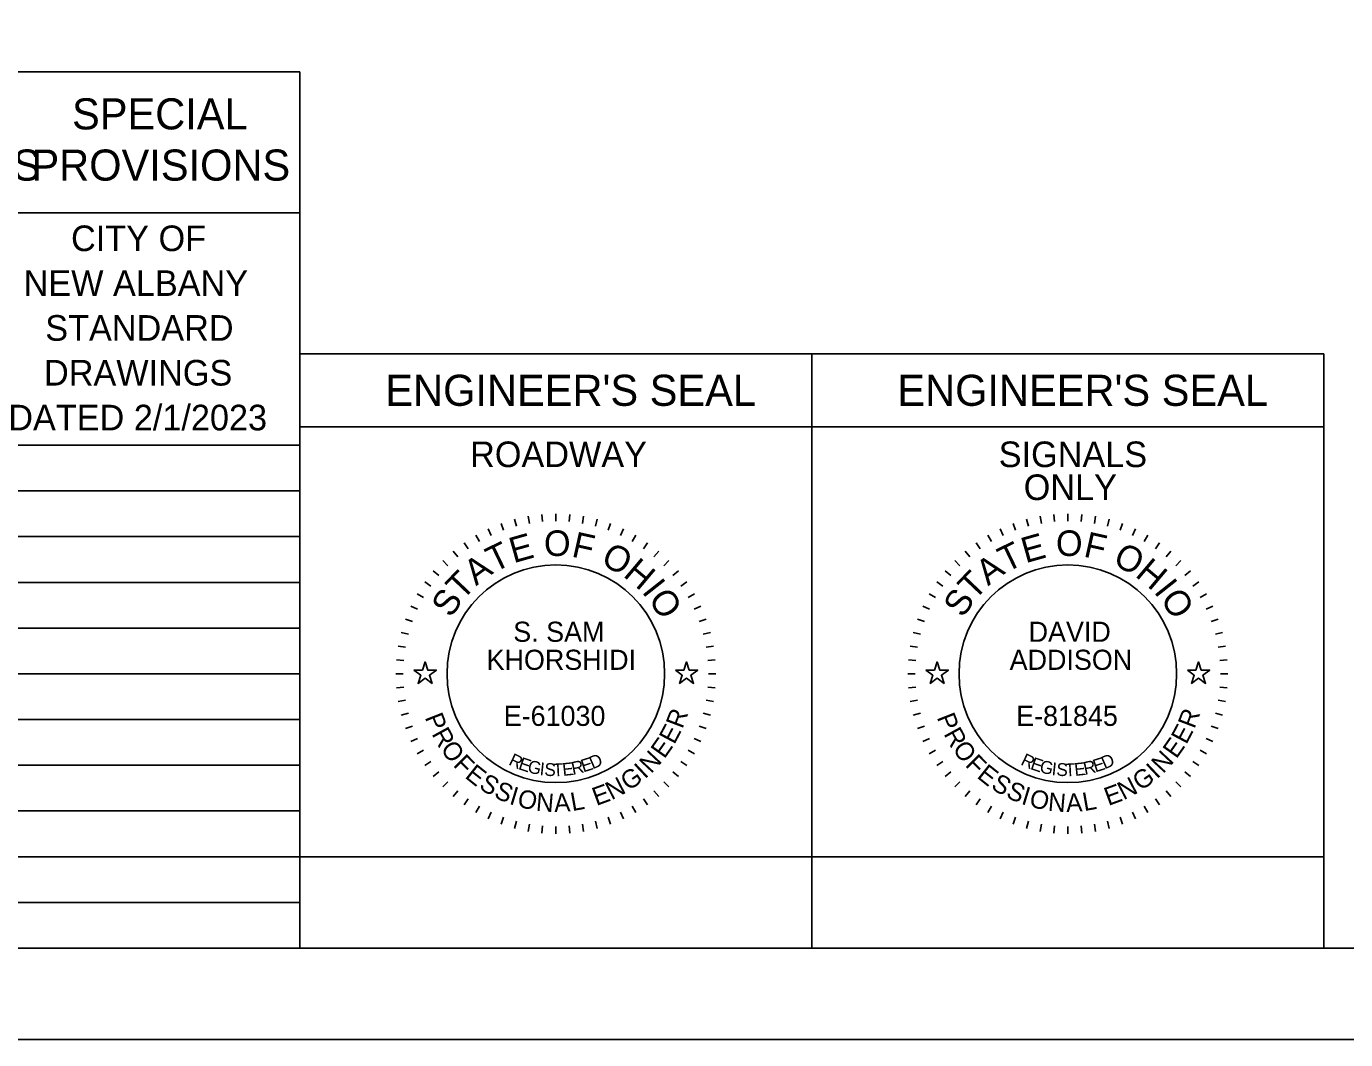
# Model space of a CAD drawing. Extents: x 0 to 91.3, y -0.7 to 22.
# Drawn here: x 22.1 to 29.32, y 0 to 5.54 of the extents above; entities that cross this region are included whole.
import ezdxf

# ---------------------------------------------------------------- set-up
doc = ezdxf.new("R2010")
doc.units = 0
for name, color, linetype in [('Default', 7, 'Continuous'), ('SH_Border', 7, 'Continuous'), ('SH_Cut_Line', 7, 'Continuous'), ('SH_Data', 7, 'Continuous'), ('SH_Text', 7, 'Continuous')]:
    doc.layers.add(name, color=color, linetype=linetype)

msp = doc.modelspace()

# ---------------------------------------------------------------- linework, layer by layer
at = {"layer": 'Default'}
for points in [[(24.2236, 2.02), (24.2705, 2.02), (24.285, 2.0645), (24.2995, 2.02), (24.3464, 2.02), (24.3085, 1.9924), (24.323, 1.9478), (24.285, 1.9754), (24.247, 1.9478), (24.2615, 1.9924)], [(25.6536, 2.02), (25.7005, 2.02), (25.715, 2.0645), (25.7295, 2.02), (25.7764, 2.02), (25.7385, 1.9924), (25.753, 1.9478), (25.715, 1.9754), (25.677, 1.9478), (25.6915, 1.9924)], [(27.0236, 2.02), (27.0705, 2.02), (27.085, 2.0645), (27.0995, 2.02), (27.1464, 2.02), (27.1085, 1.9924), (27.123, 1.9478), (27.085, 1.9754), (27.047, 1.9478), (27.0615, 1.9924)], [(28.4536, 2.02), (28.5005, 2.02), (28.515, 2.0645), (28.5295, 2.02), (28.5764, 2.02), (28.5385, 1.9924), (28.553, 1.9478), (28.515, 1.9754), (28.477, 1.9478), (28.4915, 1.9924)]]:
    msp.add_lwpolyline(points, close=True, dxfattribs=at)
at = {"layer": 'SH_Border'}
msp.add_lwpolyline([(1.5, 21.5), (33.5, 21.5), (33.5, 0.5), (1.5, 0.5)], close=True, dxfattribs=at)
at = {"layer": 'SH_Cut_Line'}
msp.add_lwpolyline([(0, 0), (34, 0), (34, 22), (0, 22)], close=True, dxfattribs=at)
at = {"layer": 'SH_Data'}
for p, q in [((10.15, 5.2917), (23.6, 5.2917)), ((23.6, 0.5), (23.6, 5.2917)), ((10.15, 4.5209), (23.6, 4.5209)), ((23.6, 0.5), (23.6, 3.75)), ((23.6, 3.75), (26.4, 3.75)), ((26.4, 3.75), (26.4, 0.5)), ((26.4, 0.5), (26.4, 3.75)), ((26.4, 3.75), (29.2, 3.75)), ((29.2, 3.75), (29.2, 0.5)), ((23.6, 3.35), (26.4, 3.35)), ((26.4, 3.35), (29.2, 3.35)), ((10.15, 3.25), (23.6, 3.25)), ((10.15, 3), (23.6, 3)), ((24.7007, 2.8222), (24.7144, 2.7846)), ((24.7735, 2.8452), (24.7839, 2.8065)), ((24.8481, 2.8617), (24.855, 2.8223)), ((24.9237, 2.8717), (24.9272, 2.8318)), ((25, 2.875), (25, 2.835)), ((25.0763, 2.8717), (25.0728, 2.8318)), ((25.1519, 2.8617), (25.145, 2.8223)), ((25.2265, 2.8452), (25.2161, 2.8065)), ((25.2993, 2.8222), (25.2856, 2.7846)), ((27.5007, 2.8222), (27.5144, 2.7846)), ((27.5735, 2.8452), (27.5839, 2.8065)), ((27.6481, 2.8617), (27.655, 2.8223)), ((27.7237, 2.8717), (27.7272, 2.8318)), ((27.8, 2.875), (27.8, 2.835)), ((27.8763, 2.8717), (27.8728, 2.8318)), ((27.9519, 2.8617), (27.945, 2.8223)), ((28.0265, 2.8452), (28.0161, 2.8065)), ((28.0993, 2.8222), (28.0856, 2.7846)), ((10.15, 2.75), (23.6, 2.75)), ((24.5625, 2.7578), (24.5825, 2.7231)), ((24.6302, 2.793), (24.6471, 2.7568)), ((25.3698, 2.793), (25.3529, 2.7568)), ((25.4375, 2.7578), (25.4175, 2.7231)), ((27.3625, 2.7578), (27.3825, 2.7231)), ((27.4302, 2.793), (27.4471, 2.7568)), ((28.1698, 2.793), (28.1529, 2.7568)), ((28.2375, 2.7578), (28.2175, 2.7231)), ((24.4376, 2.6703), (24.4633, 2.6396)), ((24.4981, 2.7168), (24.5211, 2.684)), ((25.5019, 2.7168), (25.4789, 2.684)), ((25.5624, 2.6703), (25.5367, 2.6396)), ((27.2376, 2.6703), (27.2633, 2.6396)), ((27.2981, 2.7168), (27.3211, 2.684)), ((28.3019, 2.7168), (28.2789, 2.684)), ((28.3624, 2.6703), (28.3367, 2.6396)), ((24.3813, 2.6187), (24.4096, 2.5904)), ((25.6187, 2.6187), (25.5904, 2.5904)), ((27.1813, 2.6187), (27.2096, 2.5904)), ((28.4187, 2.6187), (28.3904, 2.5904)), ((24.3297, 2.5624), (24.3604, 2.5367)), ((25.6703, 2.5624), (25.6396, 2.5367)), ((27.1297, 2.5624), (27.1604, 2.5367)), ((28.4703, 2.5624), (28.4396, 2.5367)), ((10.15, 2.5), (23.6, 2.5)), ((24.2832, 2.5019), (24.316, 2.4789)), ((25.7168, 2.5019), (25.684, 2.4789)), ((27.0832, 2.5019), (27.116, 2.4789)), ((28.5168, 2.5019), (28.484, 2.4789)), ((24.2422, 2.4375), (24.2769, 2.4175)), ((25.7578, 2.4375), (25.7231, 2.4175)), ((27.0422, 2.4375), (27.0769, 2.4175)), ((28.5578, 2.4375), (28.5231, 2.4175)), ((24.207, 2.3698), (24.2432, 2.3529)), ((25.793, 2.3698), (25.7568, 2.3529)), ((27.007, 2.3698), (27.0432, 2.3529)), ((28.593, 2.3698), (28.5568, 2.3529)), ((10.15, 2.25), (23.6, 2.25)), ((24.1778, 2.2993), (24.2154, 2.2856)), ((25.8222, 2.2993), (25.7846, 2.2856)), ((26.9778, 2.2993), (27.0154, 2.2856)), ((28.6222, 2.2993), (28.5846, 2.2856)), ((24.1548, 2.2265), (24.1935, 2.2161)), ((25.8452, 2.2265), (25.8065, 2.2161)), ((26.9548, 2.2265), (26.9935, 2.2161)), ((28.6452, 2.2265), (28.6065, 2.2161)), ((24.1383, 2.1519), (24.1777, 2.145)), ((25.8617, 2.1519), (25.8223, 2.145)), ((26.9383, 2.1519), (26.9777, 2.145)), ((28.6617, 2.1519), (28.6223, 2.145)), ((24.1283, 2.0763), (24.1682, 2.0728)), ((25.8717, 2.0763), (25.8318, 2.0728)), ((26.9283, 2.0763), (26.9682, 2.0728)), ((28.6717, 2.0763), (28.6318, 2.0728)), ((10.15, 2), (23.6, 2)), ((24.125, 2), (24.165, 2)), ((25.875, 2), (25.835, 2)), ((26.925, 2), (26.965, 2)), ((28.675, 2), (28.635, 2)), ((24.1283, 1.9237), (24.1682, 1.9272)), ((25.8717, 1.9237), (25.8318, 1.9272)), ((26.9283, 1.9237), (26.9682, 1.9272)), ((28.6717, 1.9237), (28.6318, 1.9272)), ((24.1383, 1.8481), (24.1777, 1.855)), ((25.8617, 1.8481), (25.8223, 1.855)), ((26.9383, 1.8481), (26.9777, 1.855)), ((28.6617, 1.8481), (28.6223, 1.855)), ((10.15, 1.75), (23.6, 1.75)), ((24.1548, 1.7735), (24.1935, 1.7839)), ((25.8452, 1.7735), (25.8065, 1.7839)), ((26.9548, 1.7735), (26.9935, 1.7839)), ((28.6452, 1.7735), (28.6065, 1.7839)), ((24.1778, 1.7007), (24.2154, 1.7144)), ((25.8222, 1.7007), (25.7846, 1.7144)), ((26.9778, 1.7007), (27.0154, 1.7144)), ((28.6222, 1.7007), (28.5846, 1.7144)), ((24.207, 1.6302), (24.2432, 1.6471)), ((25.793, 1.6302), (25.7568, 1.6471)), ((27.007, 1.6302), (27.0432, 1.6471)), ((28.593, 1.6302), (28.5568, 1.6471)), ((24.2422, 1.5625), (24.2769, 1.5825)), ((24.2832, 1.4981), (24.316, 1.5211)), ((25.7168, 1.4981), (25.684, 1.5211)), ((25.7578, 1.5625), (25.7231, 1.5825)), ((27.0422, 1.5625), (27.0769, 1.5825)), ((27.0832, 1.4981), (27.116, 1.5211)), ((28.5168, 1.4981), (28.484, 1.5211)), ((28.5578, 1.5625), (28.5231, 1.5825)), ((10.15, 1.5), (23.6, 1.5)), ((24.3297, 1.4376), (24.3604, 1.4633)), ((25.6703, 1.4376), (25.6396, 1.4633)), ((27.1297, 1.4376), (27.1604, 1.4633)), ((28.4703, 1.4376), (28.4396, 1.4633)), ((24.3813, 1.3813), (24.4096, 1.4096)), ((25.6187, 1.3813), (25.5904, 1.4096)), ((27.1813, 1.3813), (27.2096, 1.4096)), ((28.4187, 1.3813), (28.3904, 1.4096)), ((24.4376, 1.3297), (24.4633, 1.3604)), ((24.4981, 1.2832), (24.5211, 1.316)), ((25.5019, 1.2832), (25.4789, 1.316)), ((25.5624, 1.3297), (25.5367, 1.3604)), ((27.2376, 1.3297), (27.2633, 1.3604)), ((27.2981, 1.2832), (27.3211, 1.316)), ((28.3019, 1.2832), (28.2789, 1.316)), ((28.3624, 1.3297), (28.3367, 1.3604)), ((10.15, 1.25), (23.6, 1.25)), ((24.5625, 1.2422), (24.5825, 1.2769)), ((24.6302, 1.207), (24.6471, 1.2432)), ((25.3698, 1.207), (25.3529, 1.2432)), ((25.4375, 1.2422), (25.4175, 1.2769)), ((27.3625, 1.2422), (27.3825, 1.2769)), ((27.4302, 1.207), (27.4471, 1.2432)), ((28.1698, 1.207), (28.1529, 1.2432)), ((28.2375, 1.2422), (28.2175, 1.2769)), ((24.7007, 1.1778), (24.7144, 1.2154)), ((24.7735, 1.1548), (24.7839, 1.1935)), ((24.8481, 1.1383), (24.855, 1.1777)), ((24.9237, 1.1283), (24.9272, 1.1682)), ((25, 1.125), (25, 1.165)), ((25.0763, 1.1283), (25.0728, 1.1682)), ((25.1519, 1.1383), (25.145, 1.1777)), ((25.2265, 1.1548), (25.2161, 1.1935)), ((25.2993, 1.1778), (25.2856, 1.2154)), ((27.5007, 1.1778), (27.5144, 1.2154)), ((27.5735, 1.1548), (27.5839, 1.1935)), ((27.6481, 1.1383), (27.655, 1.1777)), ((27.7237, 1.1283), (27.7272, 1.1682)), ((27.8, 1.125), (27.8, 1.165)), ((27.8763, 1.1283), (27.8728, 1.1682)), ((27.9519, 1.1383), (27.945, 1.1777)), ((28.0265, 1.1548), (28.0161, 1.1935)), ((28.0993, 1.1778), (28.0856, 1.2154)), ((10.15, 1), (23.6, 1)), ((10.15, 0.75), (23.6, 0.75)), ((23.6, 0.5), (26.4, 0.5)), ((26.4, 0.5), (29.2, 0.5))]:
    msp.add_line(p, q, dxfattribs=at)
for points in [[(23.6, 0.5), (23.6, 1), (26.4, 1), (26.4, 0.5)], [(26.4, 0.5), (26.4, 1), (29.2, 1), (29.2, 0.5)]]:
    msp.add_lwpolyline(points, close=True, dxfattribs=at)
for centre in [(25, 2), (27.8, 2)]:
    msp.add_circle(centre, 0.595, dxfattribs=at)

# ---------------------------------------------------------------- texts
for s, height, p in [("ENGINEER'S SEAL", 0.17, (24.0676, 3.465)), ("ENGINEER'S SEAL", 0.17, (26.8676, 3.465)), ('ROADWAY', 0.14, (24.5311, 3.13)), ('SIGNALS', 0.14, (27.4219, 3.13)), ('ONLY', 0.14, (27.5585, 2.95)), ('S. SAM', 0.11, (24.7671, 2.1749)), ('DAVID', 0.11, (27.5854, 2.1749)), ('KHORSHIDI', 0.11, (24.6213, 2.0216)), ('ADDISON', 0.11, (27.4816, 2.0216)), ('E-61030', 0.11, (24.7149, 1.7151)), ('E-81845', 0.11, (27.5173, 1.7151))]:
    msp.add_text(s, height=height, dxfattribs=at).set_placement(p)
for s, height, rotation, p in [('E', 0.14, 15.75706, (24.7684, 2.6038)), ('O', 0.14, 359.78119, (24.9347, 2.6443)), ('F', 0.14, 347.43619, (25.0811, 2.6417)), ('E', 0.14, 15.75706, (27.5684, 2.6038)), ('O', 0.14, 359.78119, (27.7347, 2.6443)), ('F', 0.14, 347.43619, (27.8811, 2.6417)), ('T', 0.14, 25.71674, (24.6616, 2.5518)), ('O', 0.14, 332.25863, (25.2398, 2.6015)), ('T', 0.14, 25.71674, (27.4616, 2.5518)), ('O', 0.14, 332.25863, (28.0398, 2.6015)), ('A', 0.14, 36.47472, (24.5634, 2.4781)), ('H', 0.14, 319.91363, (25.3632, 2.5361)), ('A', 0.14, 36.47472, (27.3634, 2.4781)), ('H', 0.14, 319.91363, (28.1632, 2.5361)), ('T', 0.14, 46.4344, (24.4883, 2.3964)), ('T', 0.14, 46.4344, (27.2883, 2.3964)), ('S', 0.14, 57.19238, (24.4281, 2.3014)), ('I', 0.14, 308.36695, (25.4665, 2.4483)), ('O', 0.14, 303.14906, (25.5021, 2.4089)), ('S', 0.14, 57.19238, (27.2281, 2.3014)), ('I', 0.14, 308.36695, (28.2665, 2.4483)), ('O', 0.14, 303.14906, (28.3021, 2.4089)), ('R', 0.1, 69.23216, (25.6919, 1.6954)), ('R', 0.1, 69.23216, (28.4919, 1.6954)), ('P', 0.1, 291.49398, (24.2823, 1.7621)), ('P', 0.1, 291.49398, (27.0823, 1.7621)), ('R', 0.1, 298.73106, (24.319, 1.6717)), ('E', 0.1, 61.99508, (25.6476, 1.6098)), ('R', 0.1, 298.73106, (27.119, 1.6717)), ('E', 0.1, 61.99508, (28.4476, 1.6098)), ('O', 0.1, 306.46664, (24.3655, 1.5883)), ('E', 0.1, 54.75801, (25.5933, 1.5314)), ('O', 0.1, 306.46664, (27.1655, 1.5883)), ('E', 0.1, 54.75801, (28.3933, 1.5314)), ('F', 0.1, 314.7068, (24.4343, 1.4983)), ('R', 0.07, 334.48695, (24.7375, 1.5051)), ('E', 0.07, 341.03996, (24.7906, 1.4801)), ('G', 0.07, 347.47515, (24.8414, 1.4618)), ('I', 0.07, 353.78581, (24.9091, 1.4468)), ('E', 0.07, 6.01169, (25.0389, 1.4412)), ('R', 0.07, 11.91844, (25.0925, 1.4474)), ('E', 0.07, 17.68363, (25.1498, 1.4602)), ('D', 0.07, 23.30524, (25.201, 1.477)), ('N', 0.1, 47.02243, (25.5202, 1.4508)), ('F', 0.1, 314.7068, (27.2343, 1.4983)), ('R', 0.07, 334.48695, (27.5375, 1.5051)), ('E', 0.07, 341.03996, (27.5906, 1.4801)), ('G', 0.07, 347.47515, (27.6414, 1.4618)), ('I', 0.07, 353.78581, (27.7091, 1.4468)), ('E', 0.07, 6.01169, (27.8389, 1.4412)), ('R', 0.07, 11.91844, (27.8925, 1.4474)), ('E', 0.07, 17.68363, (27.9498, 1.4602)), ('D', 0.07, 23.30524, (28.001, 1.477)), ('N', 0.1, 47.02243, (28.3202, 1.4508)), ('E', 0.1, 321.43929, (24.4978, 1.4348)), ('S', 0.1, 328.67637, (24.5743, 1.3752)), ('S', 0.07, 356.89262, (24.9358, 1.4429)), ('T', 0.07, 3.00609, (24.9857, 1.4387)), ('G', 0.1, 35.04687, (25.3981, 1.357)), ('I', 0.1, 43.28703, (25.4868, 1.4214)), ('E', 0.1, 321.43929, (27.2978, 1.4348)), ('S', 0.1, 328.67637, (27.3743, 1.3752)), ('S', 0.07, 356.89262, (27.7358, 1.4429)), ('T', 0.07, 3.00609, (27.7857, 1.4387)), ('G', 0.1, 35.04687, (28.1981, 1.357)), ('I', 0.1, 43.28703, (28.2868, 1.4214)), ('S', 0.1, 335.91345, (24.6564, 1.3266)), ('I', 0.1, 343.15053, (24.7406, 1.2897)), ('E', 0.1, 20.07421, (25.2212, 1.277)), ('N', 0.1, 27.31129, (25.3045, 1.3075)), ('S', 0.1, 335.91345, (27.4564, 1.3266)), ('I', 0.1, 343.15053, (27.5406, 1.2897)), ('E', 0.1, 20.07421, (28.0212, 1.277)), ('N', 0.1, 27.31129, (28.1045, 1.3075)), ('O', 0.1, 346.88592, (24.7839, 1.2751)), ('N', 0.1, 355.12608, (24.8888, 1.2517)), ('A', 0.1, 2.86166, (24.9923, 1.2437)), ('L', 0.1, 10.09874, (25.0894, 1.249)), ('O', 0.1, 346.88592, (27.5839, 1.2751)), ('N', 0.1, 355.12608, (27.6888, 1.2517)), ('A', 0.1, 2.86166, (27.7923, 1.2437)), ('L', 0.1, 10.09874, (27.8894, 1.249))]:
    msp.add_text(s, height=height, rotation=rotation, dxfattribs=at).set_placement(p)
at = {"layer": 'SH_Text'}
for s, height, p in [('SPECIAL', 0.17, (22.3542, 4.9763)), ('SPECIFICATIONS', 0.17, (20.2871, 4.6963)), ('PROVISIONS', 0.17, (22.1323, 4.6963)), ('CITY OF', 0.14, (22.3487, 4.3109)), ('NEW ALBANY', 0.14, (22.0894, 4.0659)), ('STANDARD', 0.14, (22.2077, 3.8209)), ('DRAWINGS', 0.14, (22.2009, 3.5759)), ('DATED 2/1/2023', 0.14, (22.0054, 3.3309))]:
    msp.add_text(s, height=height, dxfattribs=at).set_placement(p)

doc.saveas('drawing.dxf')
